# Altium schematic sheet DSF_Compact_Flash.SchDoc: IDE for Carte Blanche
size A1; CheckedBy: SRKH; DocumentNumber: 1; SheetNumber: 1; SheetTotal: 1
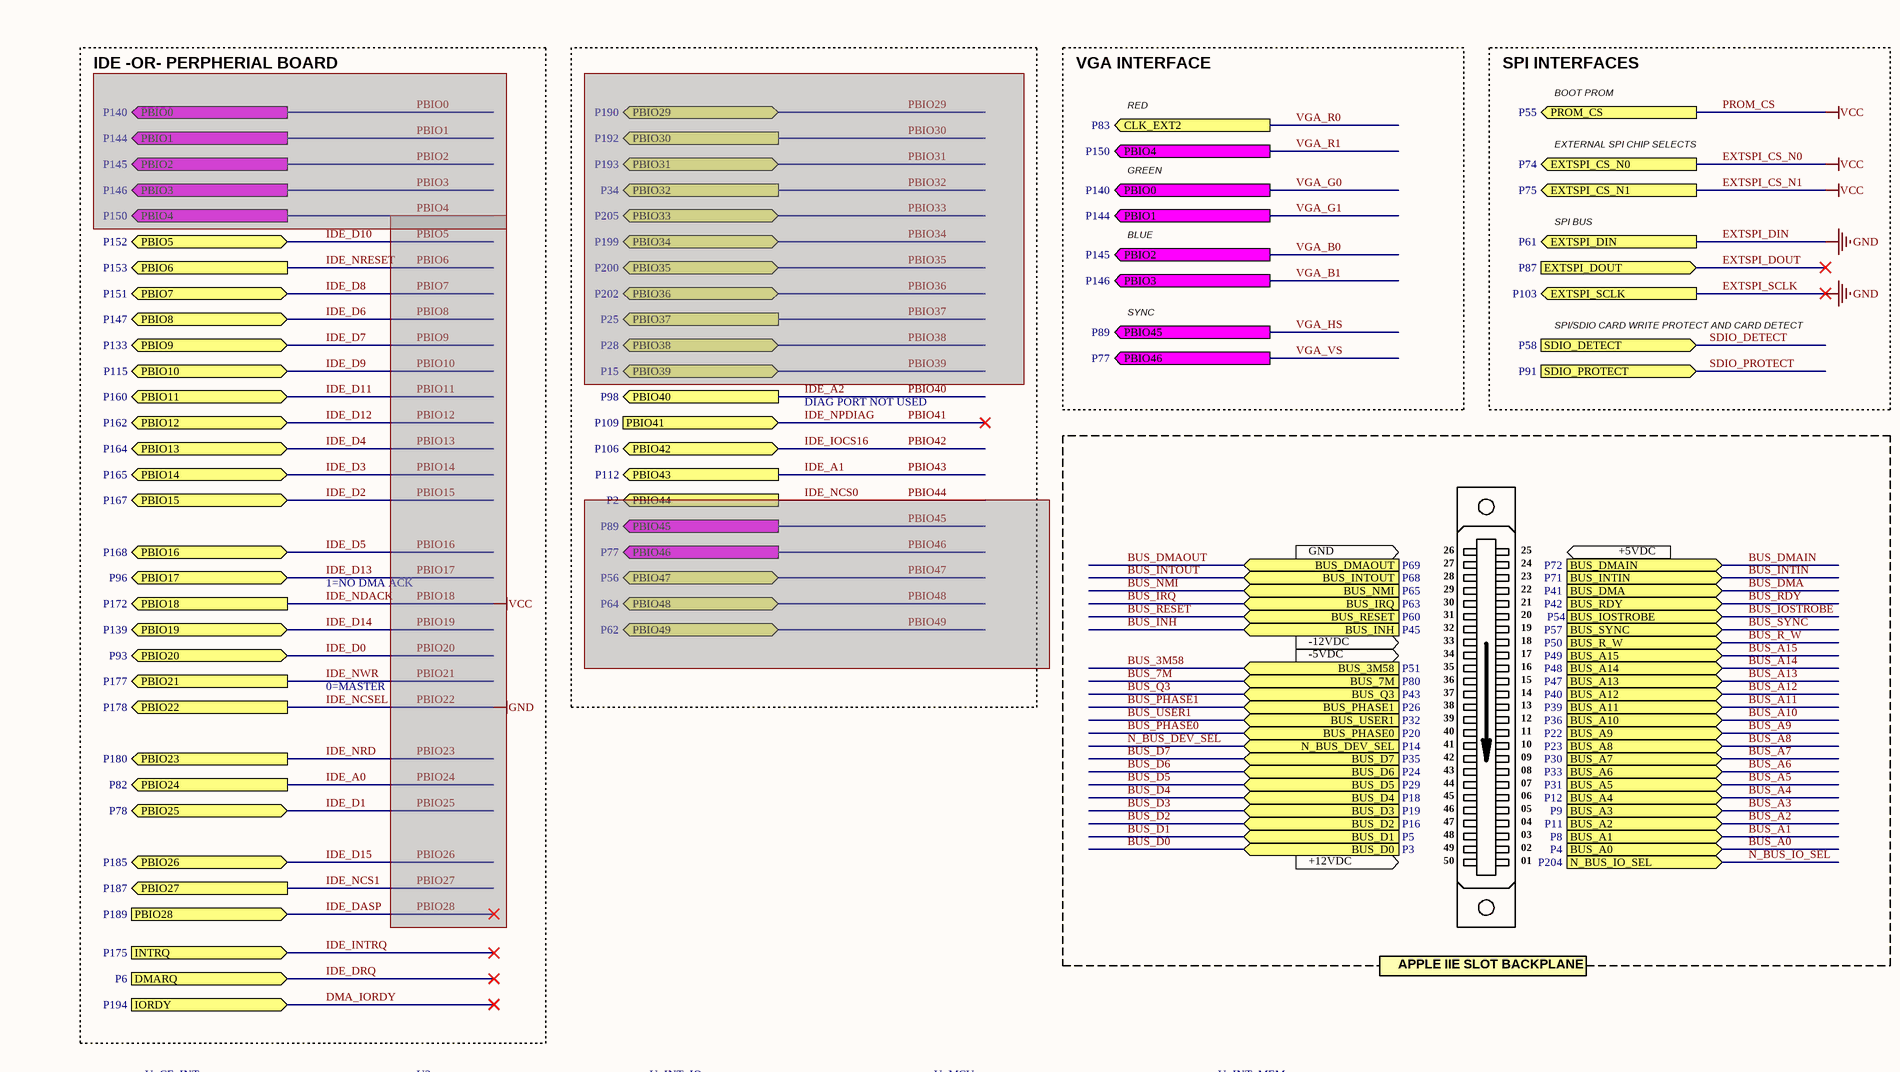
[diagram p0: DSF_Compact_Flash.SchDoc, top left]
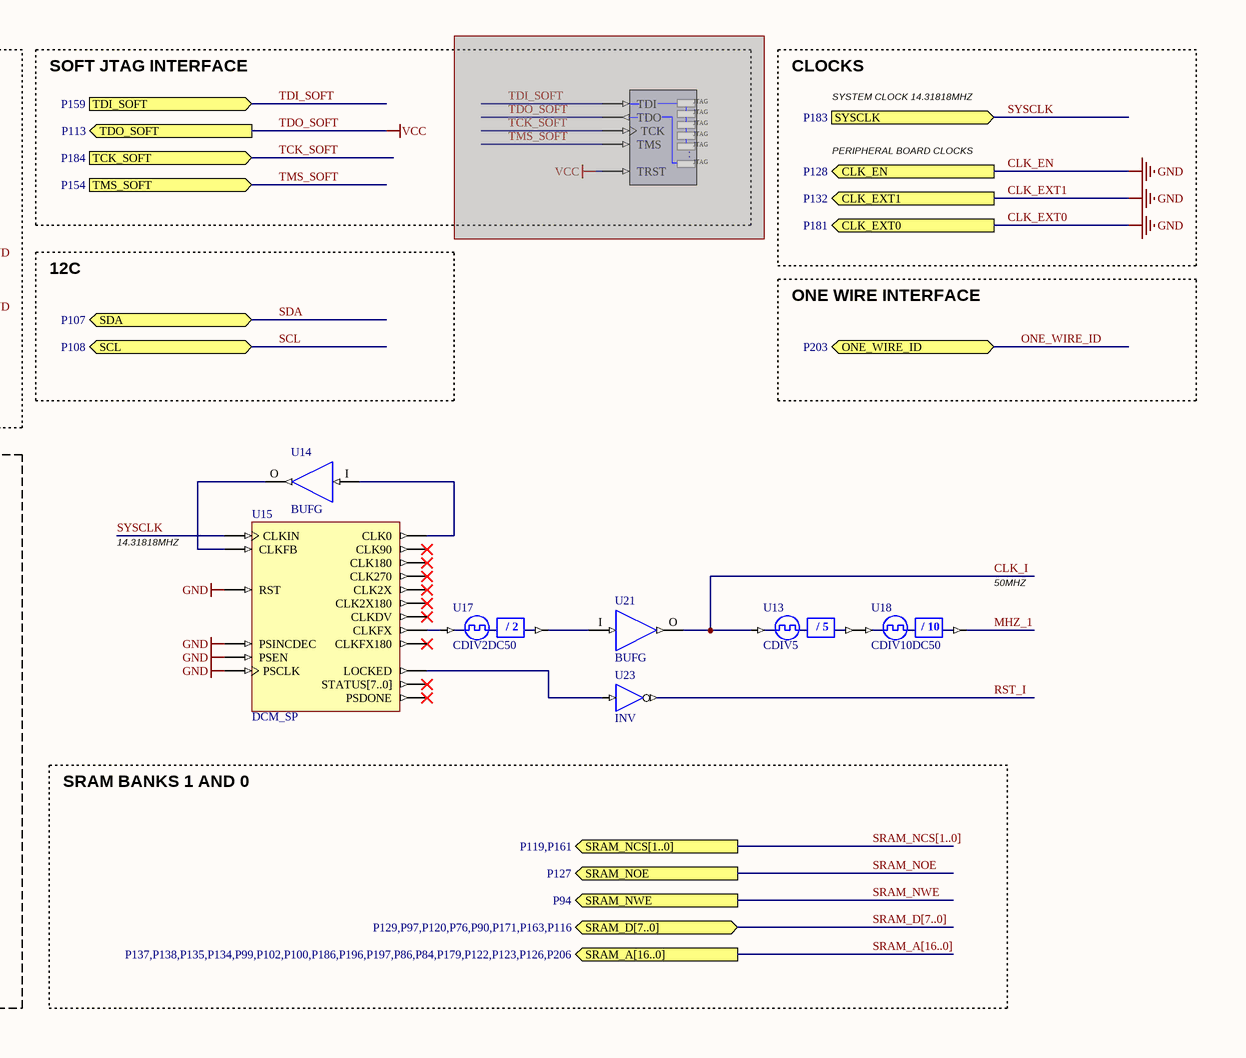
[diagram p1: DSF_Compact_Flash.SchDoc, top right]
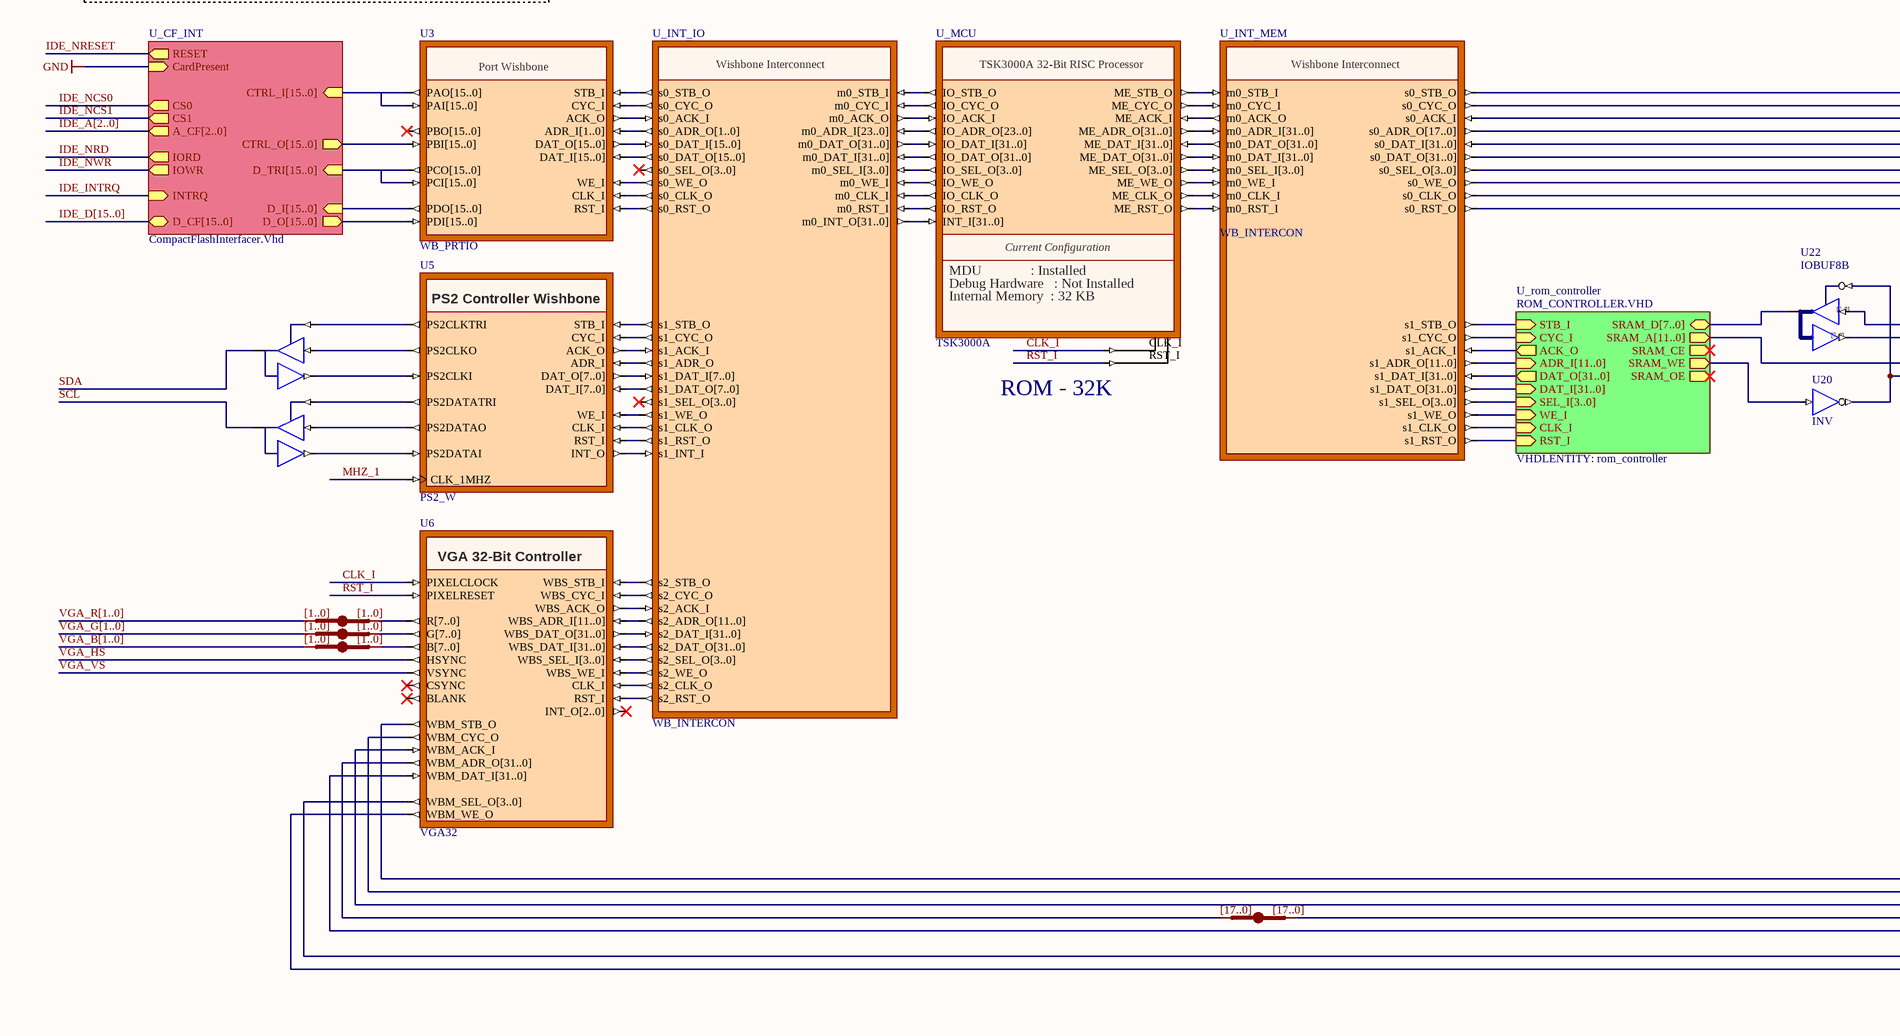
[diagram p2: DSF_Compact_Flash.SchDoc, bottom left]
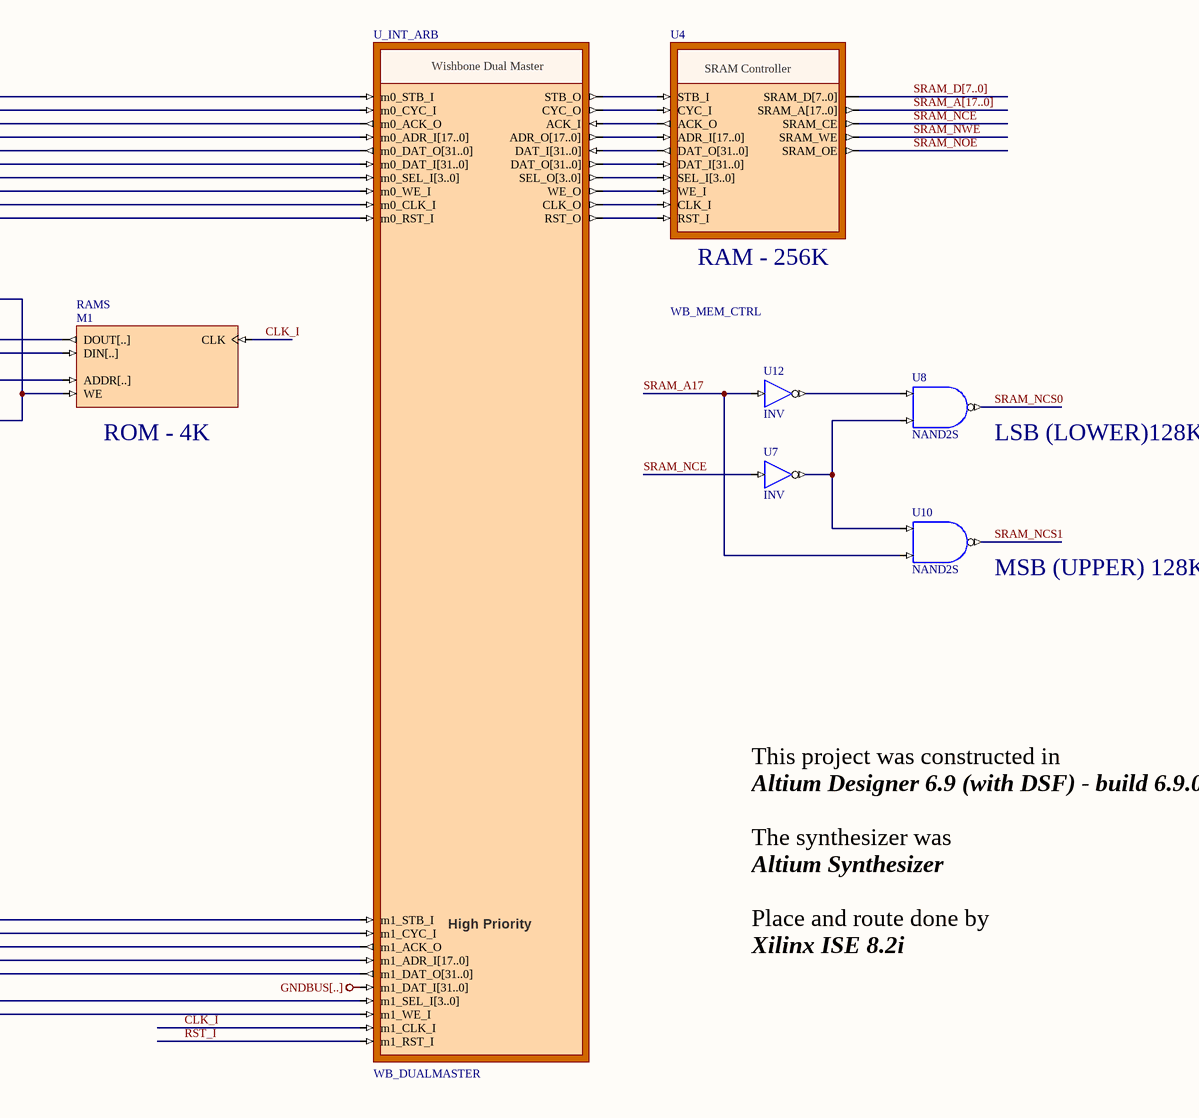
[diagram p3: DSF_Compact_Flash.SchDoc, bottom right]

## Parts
(Parts that share a designator on the sheet are numbered #1, #2 ... from top to bottom, then left to right.)
JB_AUTO?#1  IndexA: [1..0]  (hidden comment: JB)
JB_AUTO?#2  IndexA: [1..0]  (hidden comment: JB)
JB_AUTO?#3  IndexA: [1..0]  (hidden comment: JB)
JB_AUTO?#4  IndexA: [17..0]  (hidden comment: JB)
M1  RAMS
NEXUS_JTAG_PORT  NEXUS_JTAG_PORT  (value not drawn)  (masked out: inside a compile mask, not in the netlist)
U3  WB_PRTIO
U4  WB_MEM_CTRL
U5  PS2_W
U6  VGA32
U7  INV
U8  NAND2S
U9  IOBUF  (value not drawn)
U10  NAND2S
U11  IOBUF  (value not drawn)
U12  INV
U13  CDIV5
U14  BUFG
U15  DCM_SP
U17  CDIV2DC50
U18  CDIV10DC50
U20  INV
U21  BUFG
U22  IOBUF8B
U23  INV
U_INT_ARB  WB_DUALMASTER
U_INT_IO  WB_INTERCON
U_INT_MEM  WB_INTERCON
U_MCU  TSK3000A

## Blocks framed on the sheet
SOFT JTAG INTERFACE: NEXUS_JTAG_PORT

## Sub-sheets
U_CF_INT = CompactFlashInterfacer.Vhd: RESET (out), CardPresent (in), CS0 (out), CS1 (out), A_CF[2..0] (out), IORD (out), IOWR (out), INTRQ (in), D_CF[15..0] (bidir), CTRL_O[15..0] (out), CTRL_I[15..0] (in), D_TRI[15..0] (in), D_I[15..0] (in), D_O[15..0] (out)
U_rom_controller = ROM_CONTROLLER.VHD: ACK_O (out), ADR_I[11..0] (in), CLK_I (in), CYC_I (in), DAT_I[31..0] (in), DAT_O[31..0] (out), RST_I (in), SEL_I[3..0] (in), SRAM_A[11..0] (out), SRAM_CE (out), SRAM_D[7..0] (bidir), SRAM_OE (out), SRAM_WE (out), STB_I (in), WE_I (in)  | VHDLENTITY: rom_controller

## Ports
BUS_3M58 (in, see P51), BUS_7M (in, see P80), BUS_A0 (in, see P4), BUS_A1 (in, see P8), BUS_A2 (in, see P11), BUS_A3 (in, see P9), BUS_A4 (in, see P12), BUS_A5 (in, see P31), BUS_A6 (in, see P33), BUS_A7 (in, see P30), BUS_A8 (in, see P23), BUS_A9 (in, see P22), BUS_A10 (in, see P36), BUS_A11 (in, see P39), BUS_A12 (in, see P40), BUS_A13 (in, see P47), BUS_A14 (in, see P48), BUS_A15 (in, see P49), BUS_D0 (in, see P3), BUS_D1 (in, see P5), BUS_D2 (in, see P16), BUS_D3 (in, see P19), BUS_D4 (in, see P18), BUS_D5 (in, see P29), BUS_D6 (in, see P24), BUS_D7 (in, see P35), BUS_DMA (in, see P41), BUS_DMAIN (in, see P72), BUS_DMAOUT (in, see P69), BUS_INH (in, see P45), BUS_INTIN (in, see P71), BUS_INTOUT (in, see P68), BUS_IOSTROBE (in, see P54), BUS_IRQ (in, see P63), BUS_NMI (in, see P65), BUS_PHASE0 (in, see P20), BUS_PHASE1 (in, see P26), BUS_Q3 (in, see P43), BUS_R_W (in, see P50), BUS_RDY (in, see P42), BUS_RESET (in, see P60), BUS_SYNC (in, see P57), BUS_USER1 (in, see P32), CLK_EN (out, see P128), CLK_EXT0 (out, see P181), CLK_EXT1 (out, see P132), CLK_EXT2 (out, see P83), DMARQ (in, see P6), EXTSPI_CS_N0 (out, see P74), EXTSPI_CS_N1 (out, see P75), EXTSPI_DIN (out, see P61), EXTSPI_DOUT (in, see P87), EXTSPI_SCLK (out, see P103), INTRQ (in, see P175), IORDY (in, see P194), N_BUS_DEV_SEL (in, see P14), N_BUS_IO_SEL (in, see P204), ONE_WIRE_ID (bidir, see P203), PBIO0 (out, see P140), PBIO1 (out, see P144), PBIO2 (out, see P145), PBIO3 (out, see P146), PBIO4 (out, see P150), PBIO5 (bidir, see P152), PBIO6 (out, see P153), PBIO7 (bidir, see P151), PBIO8 (bidir, see P147), PBIO9 (bidir, see P133), PBIO10 (bidir, see P115), PBIO11 (bidir, see P160), PBIO12 (bidir, see P162), PBIO13 (bidir, see P164), PBIO14 (bidir, see P165), PBIO15 (bidir, see P167), PBIO16 (bidir, see P168), PBIO17 (bidir, see P96), PBIO18 (out, see P172), PBIO19 (bidir, see P139), PBIO20 (bidir, see P93), PBIO21 (out, see P177), PBIO22 (out, see P178), PBIO23 (out, see P180), PBIO24 (out, see P82), PBIO25 (bidir, see P78), PBIO26 (bidir, see P185), PBIO27 (out, see P187), PBIO28 (in, see P189), PBIO29 (bidir, see P190), PBIO30 (out, see P192), PBIO31 (bidir, see P193), PBIO32 (out, see P34), PBIO33 (bidir, see P205), PBIO34 (bidir, see P199), PBIO35 (bidir, see P200), PBIO36 (bidir, see P202), PBIO37 (out, see P25), PBIO38 (bidir, see P28), PBIO39 (bidir, see P15), PBIO40 (out, see P98), PBIO41 (in, see P109), PBIO42 (bidir, see P106), PBIO43 (out, see P112), PBIO44 (out, see P2), PBIO45 (out, see P89), PBIO46 (out, see P77), PBIO47 (bidir, see P56), PBIO48 (bidir, see P64), PBIO49 (bidir, see P62), PROM_CS (out, see P55), SCL (bidir, see P108), SDA (bidir, see P107), SDIO_DETECT (in, see P58), SDIO_PROTECT (in, see P91), SRAM_A[16..0] (out, see P137,P138,P135,P134,P99,P102,P100,P186,P196,P197,P86,P84,P179,P122,P123,P126,P206), SRAM_D[7..0] (bidir, see P129,P97,P120,P76,P90,P171,P163,P116), SRAM_NCS[1..0] (out, see P119,P161), SRAM_NOE (out, see P127), SRAM_NWE (out, see P94), SYSCLK (in, see P183), TCK_SOFT (in, see P184), TDI_SOFT (in, see P159), TDO_SOFT (out, see P113), TMS_SOFT (in, see P154)

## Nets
CLK_EN: U15.PSCLK U15.PSEN U15.PSINCDEC U15.RST ; port EXTSPI_DIN, port EXTSPI_SCLK, port CLK_EN, port CLK_EXT1, port CLK_EXT0, sheet U_CF_INT/CardPresent  [also labelled CLK_EXT0, CLK_EXT1, EXTSPI_DIN, EXTSPI_SCLK, GND]
EXTSPI_CS_N0: port PROM_CS, port EXTSPI_CS_N0, port EXTSPI_CS_N1, port TDO_SOFT  [also labelled EXTSPI_CS_N1, PROM_CS, TDO_SOFT, VCC]
GNDBUS[..]: U_INT_ARB.m1_DAT_I[31..0]
CLK_I: M1.CLK U6.PIXELCLOCK U13.CLKIN U21.O U_INT_ARB.m1_CLK_I U_MCU.CLK_I
IDE_INTRQ: port INTRQ, sheet U_CF_INT/INTRQ
IDE_NCS1: port PBIO27, sheet U_CF_INT/CS1
IDE_NRD: port PBIO23, sheet U_CF_INT/IORD
IDE_NRESET: port PBIO6, sheet U_CF_INT/RESET
IDE_NWR: port PBIO21, sheet U_CF_INT/IOWR
MHZ_1: U5.CLK_1MHZ U18.CLKDV
RST_I: U6.PIXELRESET U23.O U_INT_ARB.m1_RST_I U_MCU.RST_I
SCL: U11.IO ; port SCL
SDA: U9.IO ; port SDA
SRAM_A17: U10.I1 U12.I
SRAM_NCE: U4.SRAM_CE U7.I
SRAM_NCS0: U8.O
SRAM_NCS1: U10.O
SRAM_NOE: U4.SRAM_OE ; port SRAM_NOE
SRAM_NWE: U4.SRAM_WE ; port SRAM_NWE
SYSCLK: U15.CLKIN ; port SYSCLK
VGA_HS: U6.HSYNC ; port PBIO45
VGA_VS: U6.VSYNC ; port PBIO46
NetM1_WE: M1.WE U20.O U22.T
NetU3_ACK_O: U3.ACK_O U_INT_IO.s0_ACK_I
NetU3_CLK_I: U3.CLK_I U_INT_IO.s0_CLK_O
NetU3_CYC_I: U3.CYC_I U_INT_IO.s0_CYC_O
NetU3_RST_I: U3.RST_I U_INT_IO.s0_RST_O
NetU3_STB_I: U3.STB_I U_INT_IO.s0_STB_O
NetU3_WE_I: U3.WE_I U_INT_IO.s0_WE_O
NetU4_ACK_O: U4.ACK_O U_INT_ARB.ACK_I
NetU4_CLK_I: U4.CLK_I U_INT_ARB.CLK_O
NetU4_CYC_I: U4.CYC_I U_INT_ARB.CYC_O
NetU4_RST_I: U4.RST_I U_INT_ARB.RST_O
NetU4_STB_I: U4.STB_I U_INT_ARB.STB_O
NetU4_WE_I: U4.WE_I U_INT_ARB.WE_O
NetU5_ACK_O: U5.ACK_O U_INT_IO.s1_ACK_I
NetU5_ADR_I: U5.ADR_I U_INT_IO.s1_ADR_O
NetU5_CLK_I: U5.CLK_I U_INT_IO.s1_CLK_O
NetU5_CYC_I: U5.CYC_I U_INT_IO.s1_CYC_O
NetU5_INT_O: U5.INT_O U_INT_IO.s1_INT_I
NetU5_PS2CLKI: U5.PS2CLKI U9.O
NetU5_PS2CLKO: U5.PS2CLKO U9.I
NetU5_PS2CLKTRI: U5.PS2CLKTRI U9.T
NetU5_PS2DATAI: U5.PS2DATAI U11.O
NetU5_PS2DATAO: U5.PS2DATAO U11.I
NetU5_PS2DATATRI: U5.PS2DATATRI U11.T
NetU5_RST_I: U5.RST_I U_INT_IO.s1_RST_O
NetU5_STB_I: U5.STB_I U_INT_IO.s1_STB_O
NetU5_WE_I: U5.WE_I U_INT_IO.s1_WE_O
NetU6_CLK_I: U6.CLK_I U_INT_IO.s2_CLK_O
NetU6_RST_I: U6.RST_I U_INT_IO.s2_RST_O
NetU6_WBM_ACK_I: U6.WBM_ACK_I U_INT_ARB.m1_ACK_O
NetU6_WBM_CYC_O: U6.WBM_CYC_O U_INT_ARB.m1_CYC_I
NetU6_WBM_STB_O: U6.WBM_STB_O U_INT_ARB.m1_STB_I
NetU6_WBM_WE_O: U6.WBM_WE_O U_INT_ARB.m1_WE_I
NetU6_WBS_ACK_O: U6.WBS_ACK_O U_INT_IO.s2_ACK_I
NetU6_WBS_CYC_I: U6.WBS_CYC_I U_INT_IO.s2_CYC_O
NetU6_WBS_STB_I: U6.WBS_STB_I U_INT_IO.s2_STB_O
NetU6_WBS_WE_I: U6.WBS_WE_I U_INT_IO.s2_WE_O
NetU7_O: U7.O U8.I1 U10.I0
NetU8_I0: U8.I0 U12.O
NetU13_CLKDV: U13.CLKDV U18.CLKIN
NetU14_I: U14.I U15.CLK0
NetU14_O: U14.O U15.CLKFB
NetU15_CLKFX: U15.CLKFX U17.CLKIN
NetU15_LOCKED: U15.LOCKED U23.I
NetU17_CLKDV: U17.CLKDV U21.I
NetU20_I: U20.I ; sheet U_rom_controller/SRAM_WE
NetU_INT_ARB_m0_ACK_O: U_INT_ARB.m0_ACK_O U_INT_MEM.s0_ACK_I
NetU_INT_ARB_m0_CLK_I: U_INT_ARB.m0_CLK_I U_INT_MEM.s0_CLK_O
NetU_INT_ARB_m0_CYC_I: U_INT_ARB.m0_CYC_I U_INT_MEM.s0_CYC_O
NetU_INT_ARB_m0_RST_I: U_INT_ARB.m0_RST_I U_INT_MEM.s0_RST_O
NetU_INT_ARB_m0_STB_I: U_INT_ARB.m0_STB_I U_INT_MEM.s0_STB_O
NetU_INT_ARB_m0_WE_I: U_INT_ARB.m0_WE_I U_INT_MEM.s0_WE_O
NetU_INT_IO_m0_ACK_O: U_INT_IO.m0_ACK_O U_MCU.IO_ACK_I
NetU_INT_IO_m0_CLK_I: U_INT_IO.m0_CLK_I U_MCU.IO_CLK_O
NetU_INT_IO_m0_CYC_I: U_INT_IO.m0_CYC_I U_MCU.IO_CYC_O
NetU_INT_IO_m0_RST_I: U_INT_IO.m0_RST_I U_MCU.IO_RST_O
NetU_INT_IO_m0_STB_I: U_INT_IO.m0_STB_I U_MCU.IO_STB_O
NetU_INT_IO_m0_WE_I: U_INT_IO.m0_WE_I U_MCU.IO_WE_O
NetU_INT_MEM_m0_ACK_O: U_INT_MEM.m0_ACK_O U_MCU.ME_ACK_I
NetU_INT_MEM_m0_CLK_I: U_INT_MEM.m0_CLK_I U_MCU.ME_CLK_O
NetU_INT_MEM_m0_CYC_I: U_INT_MEM.m0_CYC_I U_MCU.ME_CYC_O
NetU_INT_MEM_m0_RST_I: U_INT_MEM.m0_RST_I U_MCU.ME_RST_O
NetU_INT_MEM_m0_STB_I: U_INT_MEM.m0_STB_I U_MCU.ME_STB_O
NetU_INT_MEM_m0_WE_I: U_INT_MEM.m0_WE_I U_MCU.ME_WE_O
NetU_INT_MEM_s1_ACK_I: U_INT_MEM.s1_ACK_I ; sheet U_rom_controller/ACK_O
NetU_INT_MEM_s1_CLK_O: U_INT_MEM.s1_CLK_O ; sheet U_rom_controller/CLK_I
NetU_INT_MEM_s1_CYC_O: U_INT_MEM.s1_CYC_O ; sheet U_rom_controller/CYC_I
NetU_INT_MEM_s1_RST_O: U_INT_MEM.s1_RST_O ; sheet U_rom_controller/RST_I
NetU_INT_MEM_s1_STB_O: U_INT_MEM.s1_STB_O ; sheet U_rom_controller/STB_I
NetU_INT_MEM_s1_WE_O: U_INT_MEM.s1_WE_O ; sheet U_rom_controller/WE_I

Not connected (* = marked no-connect by the designer): JB_AUTO?#1 A[0..0] B[0..0]; JB_AUTO?#2 A[0..0] B[0..0]; JB_AUTO?#3 A[0..0] B[0..0]; JB_AUTO?#4 A[0..0] B[0..0]; M1 ADDR[..] DIN[..] DOUT[..]; U3 ADR_I[1..0] DAT_I[15..0] DAT_O[15..0] PAI[15..0] PAO[15..0] PBI[15..0] PBO[15..0]* PCI[15..0] PCO[15..0] PDI[15..0] PDO[15..0]; U4 ADR_I[17..0] DAT_I[31..0] DAT_O[31..0] SEL_I[3..0] SRAM_A[17..0] SRAM_D[7..0]; U5 DAT_I[7..0] DAT_O[7..0]; U6 B[7..0] BLANK* CSYNC* G[7..0] INT_O[2..0]* R[7..0] WBM_ADR_O[31..0] WBM_DAT_I[31..0] WBM_SEL_O[3..0] WBS_ADR_I[11..0] WBS_DAT_I[31..0] WBS_DAT_O[31..0] WBS_SEL_I[3..0]; U15 CLK2X* CLK2X180* CLK90* CLK180* CLK270* CLKDV* CLKFX180* PSDONE* STATUS[7..0]*; U22 I[7..0] IO[7..0] O[7..0]; U_INT_ARB ADR_O[17..0] DAT_I[31..0] DAT_O[31..0] m0_ADR_I[17..0] m0_DAT_I[31..0] m0_DAT_O[31..0] m0_SEL_I[3..0] m1_ADR_I[17..0] m1_DAT_O[31..0] m1_SEL_I[3..0] SEL_O[3..0]; U_INT_IO m0_ADR_I[23..0] m0_DAT_I[31..0] m0_DAT_O[31..0] m0_INT_O[31..0] m0_SEL_I[3..0] s0_ADR_O[1..0] s0_DAT_I[15..0] s0_DAT_O[15..0] s0_SEL_O[3..0]* s1_DAT_I[7..0] s1_DAT_O[7..0] s1_SEL_O[3..0]* s2_ADR_O[11..0] s2_DAT_I[31..0] s2_DAT_O[31..0] s2_SEL_O[3..0]; U_INT_MEM m0_ADR_I[31..0] m0_DAT_I[31..0] m0_DAT_O[31..0] m0_SEL_I[3..0] s0_ADR_O[17..0] s0_DAT_I[31..0] s0_DAT_O[31..0] s0_SEL_O[3..0] s1_ADR_O[11..0] s1_DAT_I[31..0] s1_DAT_O[31..0] s1_SEL_O[3..0]; U_MCU INT_I[31..0] IO_ADR_O[23..0] IO_DAT_I[31..0] IO_DAT_O[31..0] IO_SEL_O[3..0] ME_ADR_O[31..0] ME_DAT_I[31..0] ME_DAT_O[31..0] ME_SEL_O[3..0]

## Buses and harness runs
bus IDE_A[2..0] = sheet U_CF_INT/A_CF[2..0]
bus IDE_D[15..0] = sheet U_CF_INT/D_CF[15..0]
bus SRAM_A[16..0] = port SRAM_A[16..0]
bus SRAM_A[17..0]
bus SRAM_D[7..0]
bus SRAM_D[7..0] = port SRAM_D[7..0]
bus SRAM_NCS[1..0] = port SRAM_NCS[1..0]
bus VGA_B[1..0]
bus VGA_G[1..0]
bus VGA_R[1..0]

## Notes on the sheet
- IDE -OR- PERPHERIAL BOARD
- VGA INTERFACE
- RED
- SPI INTERFACES
- BOOT PROM
- CLOCKS
- SYSTEM CLOCK 14.31818MHZ
- GREEN
- EXTERNAL SPI CHIP SELECTS
- PERIPHERAL BOARD CLOCKS
- BLUE
- SPI BUS
- SYNC
- 12C
- ONE WIRE INTERFACE
- SPI/SDIO CARD WRITE PROTECT AND CARD DETECT
- DIAG PORT NOT USED
- GND
- 26
- 27
- 28
- 25
- 24
- 23
- +5VDC
- 14.31818MHZ
- 50MHZ
- 1=NO DMA ACK
- 29
- 30
- 31
- 32
- 33
- 22
- 21
- 20
- 19
- 18
- 0=MASTER
- -12VDC
- -5VDC
- 34
- 35
- 36
- 37
- 38
- 17
- 16
- 15
- 14
- 13
- 39
- 40
- 41
- 42
- 43
- 12
- 11
- 10
- 09
- 08
- SRAM BANKS 1 AND 0
- 44
- 45
- 46
- 47
- 48
- 07
- 06
- 05
- 04
- 03
- +12VDC
- 49
- 50
- 02
- 01
- APPLE IIE SLOT BACKPLANE
- (near U4) RAM - 256K
- (near U_MCU) ROM - 32K
- (near M1) ROM - 4K
- (near U8) LSB (LOWER)128K
- (near U10) MSB (UPPER) 128K
- Altium Designer 6.9 (with DSF) - build 6.9.0.12380
- This project was constructed in
- The synthesizer was
- Altium Synthesizer
- Place and route done by
- Xilinx ISE 8.2i

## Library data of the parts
JB_AUTO?#1-JB_AUTO?#4 = JB: System BUS Joiner
M1 = RAMS: Single Port Random Access Memory; Memory_Depth: DefinedBy=ADDR; Memory_Type: RAM_SinglePortBlock; Memory_Width: DefinedBy=DIN; Memory_ClockEdge: Rising; Nexus_Core: Memory_Program; Memory_ContentFile: .\Embedded\EmbOut\idecontroller_system_ROM_INT2.hex; SubClass: RAM
NEXUS_JTAG_PORT = NEXUS_JTAG_PORT: Soft Nexus-Chain Connector; NEXUS_JTAG_CONNECTOR: True
U3 = WB_PRTIO: Configurable Port Wishbone; ChildModel: PRTIO4X16_W; ConfigurationParameters: {}PortCount[4]{}BusWidth[16]{}PortKind[0]{}; UseInDSF: True
U4 = WB_MEM_CTRL: Configurable Memory Controller; ConfigurationParameters: {}Version[1.0]{}Option_MemoryType[Asynchronous SRAM]{}Option_MemorySize[256 KB (64K x 32-bit)]{}Option_Layout[1 x  8-bit Wide Device]{}Option_Read[2]{}Option_WriteSetup[1]{}Option_WritePulse[1]{}Option_WriteHold[1]{}Option_FlashRead[4]{}Option_FlashWriteSetup[1]{}Option_FlashWritePulse[5]{}Option_FlashWriteHold[1]{}Option_SdramKeepRowOpen[0]{}Option_SdramClock[100]{}Option_SdramWriteRecovery[4]{}Option_SdramAutoRefresh[16]{}Option_SdramActiveToReadWrite[8]{}Option_SdramPrecharge[16]{}Option_SdramCasLatency[2]{}Option_SdramClockScheme[0]{}; UseInDSF: True
U5 = PS2_W: PS2 Controller Wishbone; UseInDSF: True
U6 = VGA32: VGA 32-Bit Controller; UseInDSF: True
U7 U12 U20 U23 = INV: Inverter; FunctionalClass: Logic Primitive; ArchiveName: GENERIC; VHDLIB_SIM: GENERIC_LIB
U8 U10 = NAND2S: 2-Input NAND Gate, Single Pin Version; XilinxEquivalent: NAND2; FunctionalClass: Logic Primitive; PortSize: 2; ArchiveName: GENERIC; VHDLIB_SIM: GENERIC_LIB
U9 U11 = IOBUF: Input/Output Buffer; Enable: Low; Control: Common Control T; ArchiveName: GENERIC; VHDLIB_SIM: GENERIC_LIB
U13 = CDIV5: Clock Divider by 5; DivisorRate: 5; ArchiveName: GENERIC; VHDLIB_SIM: GENERIC_LIB
U14 U21 = BUFG: Global Clock Buffer; FPGAVendor: Xilinx
U15 = DCM_SP: Digital Clock Manager; FPGAVendor: Xilinx; CLKFX_MULTIPLY: 7
U17 = CDIV2DC50: Clock Divider by 2 with 50% Duty Cycle Output; DivisorRate: 2; ArchiveName: GENERIC; VHDLIB_SIM: GENERIC_LIB; XilinxEquivalent: CLK_DIV2; DutyCycle: 50
U18 = CDIV10DC50: Clock Divider by 10 with 50% Duty Cycle Output; DivisorRate: 10; ArchiveName: GENERIC; VHDLIB_SIM: GENERIC_LIB; XilinxEquivalent: CLK_DIV10; DutyCycle: 50
U22 = IOBUF8B: 8-Bit Input/Output Buffer, Bus Version; SubClass: IOBUF; Enable: Low; Control: Common Control T; PortSize: 8; ArchiveName: GENERIC; VHDLIB_SIM: GENERIC_LIB
U_INT_ARB = WB_DUALMASTER: Configurable Wishbone Dual Master; ConfigurationParameters: {}Version[1.0]{}DataWidth[0]{}AddressWidth[18]{}SpaceAfter[52]{}DualType[1]{}PriorityDevice[1]
U_INT_IO = WB_INTERCON: Configurable Wishbone Interconnect; ConfigurationParameters: {}Version[1.0]{}UnusedInterrupts[1]{}MasterAddressBits[1]{}Name0[CF]{}Kind0[0]{}SpaceAfter0[8]{}Address_Base0[0]{}Address_Bits0[2]{}Address_Mode0[0]{}Address_DecodeWidth0[4]{}DataWidth0[1]{}UsedInterrupts0[ ]{}Name1[PS2]{}Kind1[0]{}SpaceAfter1[10]{}Address_Base1[4194304]{}Address_Bits1[1]{}Address_Mode1[1]{}Address_DecodeWidth1[4]{}DataWidth1[2]{}UsedInterrupts1[E6]{}Name2[VGA]{}Kind2[0]{}SpaceAfter2[0]{}Address_Base2[8388608]{}Address_Bits2[12]{}Address_Mode2[1]{}Address_DecodeWidth2[4]{}DataWidth2[0]{}UsedInterrupts2[ ]
U_INT_MEM = WB_INTERCON: Configurable Wishbone Interconnect; ConfigurationParameters: {}Version[1.0]{}UnusedInterrupts[2]{}MasterAddressBits[0]{}Name0[SRAM_DB]{}Kind0[2]{}SpaceAfter0[8]{}Address_Base0[16777216]{}Address_Bits0[18]{}Address_Mode0[1]{}Address_DecodeWidth0[8]{}DataWidth0[0]{}UsedInterrupts0[ ]{}Name1[ROM_INT2]{}Kind1[1]{}SpaceAfter1[4]{}Address_Base1[33554432]{}Address_Bits1[12]{}Address_Mode1[1]{}Address_DecodeWidth1[8]{}DataWidth1[0]{}UsedInterrupts1[ ]
U_MCU = TSK3000A: TSK3000A OCD Microprocessor; Nexus_JTAG_Device: False; Nexus_Core: Processor_Normal; Nexus_JTAG_Order: 10; ProgramLogicalTopAddress: 0; ConfigurationParameters: {}Version[1.0]{}Option_Processor[0]{}Option_Memory[5]{}Option_MDU[0]{}Option_OCDS[1]{}Option_Shifter[0]{}Option_InterruptCount[32]{}Option_DebugWhenReset[0]{}; Memory_Configuration: Record[AUTOIMPORT]{}AutoImport_Peripherals[False]{}AutoImport_Memory[False]{n}Record[PHYSICAL_MEMORY]{}ComponentDesignator[U_MCU]{}Memory_Depth[32768]{}Memory_UsageType[rom]{}ProgramDownloadAddress[0x00000000]{}Memory_BusType[TSK3000:addr_bus]{}Memory_Mau[0x00000008]{}Memory_MatchedComponent[]{}Memory_Description[]{}Memory_FillBitPattern[]{}Memory_IncludeDependencies[False]{}Memory_ByLoadAddress[False]{}Memory_Interrupts[]{n}Record[PHYSICAL_MEMORY]{}ComponentDesignator[SRAM_DB]{}Memory_Depth[0x40000]{}Memory_UsageType[ram]{}ProgramDownloadAddress[0x1000000]{}Memory_BusType[TSK3000:addr_bus]{}Memory_Mau[0x00000008]{}Memory_MatchedComponent[]{}Memory_Description[U_INT_MEM]{}Memory_FillBitPattern[]{}Memory_IncludeDependencies[False]{}Memory_ByLoadAddress[False]{}Memory_Interrupts[]{n}Record[PHYSICAL_MEMORY]{}ComponentDesignator[ROM_INT2]{}Memory_Depth[0x1000]{}Memory_UsageType[rom]{}ProgramDownloadAddress[0x2000000]{}Memory_BusType[TSK3000:addr_bus]{}Memory_Mau[0x00000008]{}Memory_MatchedComponent[]{}Memory_Description[U_INT_MEM]{}Memory_FillBitPattern[]{}Memory_IncludeDependencies[False]{}Memory_ByLoadAddress[False]{}Memory_Interrupts[]{n}Record[CODE_EXPORT]{}ExportType[1]{n}Record[NEXUS_CORE]{}ComponentDesignator[U_MCU]{}Memory_Depth[32768]{}Memory_UsageType[rom]{}ProgramDownloadAddress[0x00000000]{}Memory_BusType[TSK3000:addr_bus]{}Memory_Mau[0x00000008]{}Memory_MatchedComponent[]{}Memory_Description[]{}Memory_FillBitPattern[]{}Memory_IncludeDependencies[False]{}Memory_ByLoadAddress[False]{}Memory_Interrupts[]{n}Record[NEXUS_CORE]{}ComponentDesignator[SRAM_DB]{}Memory_Depth[0x40000]{}Memory_UsageType[ram]{}ProgramDownloadAddress[0x1000000]{}Memory_BusType[TSK3000:addr_bus]{}Memory_Mau[0x00000008]{}Memory_MatchedComponent[]{}Memory_Description[U_INT_MEM]{}Memory_FillBitPattern[]{}Memory_IncludeDependencies[False]{}Memory_ByLoadAddress[False]{}Memory_Interrupts[]{n}Record[NEXUS_CORE]{}ComponentDesignator[ROM_INT2]{}Memory_Depth[0x1000]{}Memory_UsageType[rom]{}ProgramDownloadAddress[0x2000000]{}Memory_BusType[TSK3000:addr_bus]{}Memory_Mau[0x00000008]{}Memory_MatchedComponent[]{}Memory_Description[U_INT_MEM]{}Memory_FillBitPattern[]{}Memory_IncludeDependencies[False]{}Memory_ByLoadAddress[False]{}Memory_Interrupts[]{n}Record[PERIPHERAL]{}ComponentDesignator[CF]{}Memory_Depth[0x0004]{}Memory_UsageType[peripheral]{}ProgramDownloadAddress[0xFF000000]{}Memory_BusType[TSK3000:addr_bus]{}Memory_Mau[8]{}Memory_MatchedComponent[]{}Memory_Description[U_INT_IO]{}Memory_FillBitPattern[]{}Memory_IncludeDependencies[False]{}Memory_ByLoadAddress[False]{}Memory_Interrupts[]{n}Record[PERIPHERAL]{}ComponentDesignator[PS2]{}Memory_Depth[0x0002]{}Memory_UsageType[peripheral]{}ProgramDownloadAddress[0xFF400000]{}Memory_BusType[TSK3000:addr_bus]{}Memory_Mau[8]{}Memory_MatchedComponent[]{}Memory_Description[U_INT_IO]{}Memory_FillBitPattern[]{}Memory_IncludeDependencies[False]{}Memory_ByLoadAddress[False]{}Memory_Interrupts[E6]{n}Record[PERIPHERAL]{}ComponentDesignator[VGA]{}Memory_Depth[0x1000]{}Memory_UsageType[peripheral]{}ProgramDownloadAddress[0xFF800000]{}Memory_BusType[TSK3000:addr_bus]{}Memory_Mau[8]{}Memory_MatchedComponent[]{}Memory_Description[U_INT_IO]{}Memory_FillBitPattern[]{}Memory_IncludeDependencies[False]{}Memory_ByLoadAddress[False]{}Memory_Interrupts[]{n}; ConfiguratorName: FPGA_MCU32; ChildModel1: TSK3000A_MCU; ChildModel2: TSK3000A_MDU; ChildModel3: TSK3000A_OCDS; ChildModel4: TSK3000A_Shift_Barrel; ChildModel5: TSK3000A_Shift_Sequential; ChildModel6: Mult_32x32; ChildModel7: m33x33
